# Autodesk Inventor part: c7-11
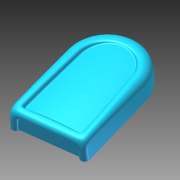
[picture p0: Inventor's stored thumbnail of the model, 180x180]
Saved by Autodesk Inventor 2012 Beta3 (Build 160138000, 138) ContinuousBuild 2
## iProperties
Created: 2010-12
Part Number: c7-11
Material: Default
Document SubType Name: Modeling
Designer: Beta-8540w
Density: 1 g/cm^3
Author: Beta-8540w
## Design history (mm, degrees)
sketch "Sketch1"
  geometry: L1 (-25, 0)-(25, 0); L2 (25, 0)-(25, 80); L3 (25, 80)-(-25, 80); L4 (-25, 80)-(-25, 0); 2 further points
  constraints: 8 end point, 2 parallel, 1 coincident, 1 horizontal, 1 midpoint, 1 perpendicular
  dimensions: "d0" = 50 distance of L3.end L2.end; "d1" = 80 distance of L2.end L1.end
extrude "Extrusion1" new body sketch "Sketch1" distance "d2" = 15; taper "d3" = 0 deg
feature "FaceDraft1" dims angle "d4" = -2 deg
fillet "Fillet1"
fillet "Fillet2" dims "d5" = 8, "d6" = 8, "d7" = 8, "d8" = 8, "d9" = 8, "d10" = 8, "d11" = 3, "d12" = 3, "d13" = 3, "d14" = 6, "d15" = 5
sketch "Sketch2"
  geometry: L1 (5.522, 12)-(38.474, 12) reference; L2 (0, 0)-(43.996, 0) reference; L3 (41.757, 6.83)-(41.995, 0); L4 (41.925, 2)-(2.071, 2); L5 (2.001, 0)-(2.24, 6.83); L6 (5.522, 10)-(38.474, 10); A1 r 5.284 centre (38.474, 6.716) between (43.755, 6.9) and (38.474, 12) reference; A2 r 5.284 centre (5.522, 6.716) between (5.522, 12) and (0.241, 6.9) reference; A3 r 3.284 centre (38.474, 6.716) between (41.757, 6.83) and (38.474, 10); A4 r 3.284 centre (5.522, 6.716) between (5.522, 10) and (2.24, 6.83); 1 further point
  constraints: 8 end point, 4 point on circle, 4 point on line, 2 centre point, 1 other
  dimensions: "d16" = 2 radial gap between concentric circles of A2 A4
extrude "Extrusion2" cut sketch "Sketch2" distance "d17" = 2; taper "d18" = 0 deg
feature "FaceDraft2" dims angle "d19" = 15 deg
sketch "Sketch3" dims "d20" = 2.5
  geometry: L1 (16.476, 3)-(-16.476, 3) reference; L2 (16.476, 5.5)-(-16.476, 5.5); 9 further points
  constraints: 2 end point, 2 parallel, 1 horizontal alignment, 19 other
extrude "Extrusion3" cut sketch "Sketch3" distance "d21" = 3; taper "d22" = 0 deg
feature "FaceDraft3" dims angle "d23" = 10 deg
workplane "Work Plane1"
sketch "Sketch4"
  geometry: L1 (41.1, -1.222)-(41.476, -12) reference; L2 (41.476, -12)-(-8.524, -12) reference; L3 (-8.524, -12)-(-8.147, -1.222) reference; L4 (-3.776, 3)-(-1.272, 3) reference; L5 (-0.743, 0)-(33.695, 0) reference; L6 (34.225, 3)-(36.728, 3) reference; L7 (-11.024, -1.856)-(43.976, -1.856); A1 r 100 centre (16.476, -98) between (43.976, -1.856) and (-11.024, -1.856); 2 further points
  constraints: 2 end point, 2 point on circle, 1 centre point, 1 midpoint, 1 parallel, 1 vertical alignment, 4 other
  dimensions: "d25" = 100 radius of A1; "d26" = 14 distance edge to line of A1 L2; "d27" = 55 distance of L7.start L7.end
extrude_surface "ExtrusionSrf1" sketch "Sketch4" dims "d28" = 86, "d29" = 0
feature "Replace Face1"
fillet "Fillet3" dims "d34" = 1, "d35" = 2
body "Solid1"
body "Srf1"
node "Project Cut Edges1"
